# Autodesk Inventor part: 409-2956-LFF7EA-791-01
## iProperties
Shininess: 64.0
Angle Display Precision: 2
Document Length Units: 11272
Document Angle Units: 11279
Document Time Units: 11290
Document Mass Units: 11286
Document Length Units Precision: 3
Document Angle Units Precision: 2
Compacted: True
Created: 2002-04
Part Number: 409-2956-LFF7EA-791-01
Description: DISCHARGE PIPE STAND ANGLE
Document SubType Name: Modeling
Designer: S. Boerckel
Mass: 4144.19 g
Surface Area: 1729.53 cm^2
Volume: 527.922 cm^3
Density: 7.85 g/cm^3
Cost Center: 2 x 2 x 1/4 ANGLE
Material: ASTM A36
Engineer: S. Boerckel
Density: 0.0
Volumn: 0.0
Area: 0.0
PropertySet Name: Model Information
Control State: 0
Master: False
Checked Out: False
length: 34.440 in
SMR: =<COST CENTER> - <MATERIAL>
Author: S. Boerckel
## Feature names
1. Extrusion1
